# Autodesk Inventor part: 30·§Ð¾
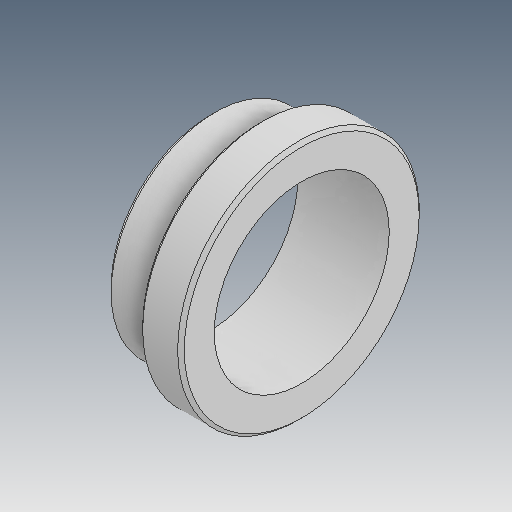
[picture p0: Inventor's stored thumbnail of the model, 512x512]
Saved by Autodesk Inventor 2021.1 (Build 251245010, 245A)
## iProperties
Created: 2019-05
Part Number: 30·§Ð¾
Material: Ogólny
Document SubType Name: Modeling
Designer: user
Density: 1 g/cm^3
Appearance: Domyślna
Author: user
Revision Number: ÈÎºÎ
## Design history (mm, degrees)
feature "ÊäÈë1"
node "Bryła1"
